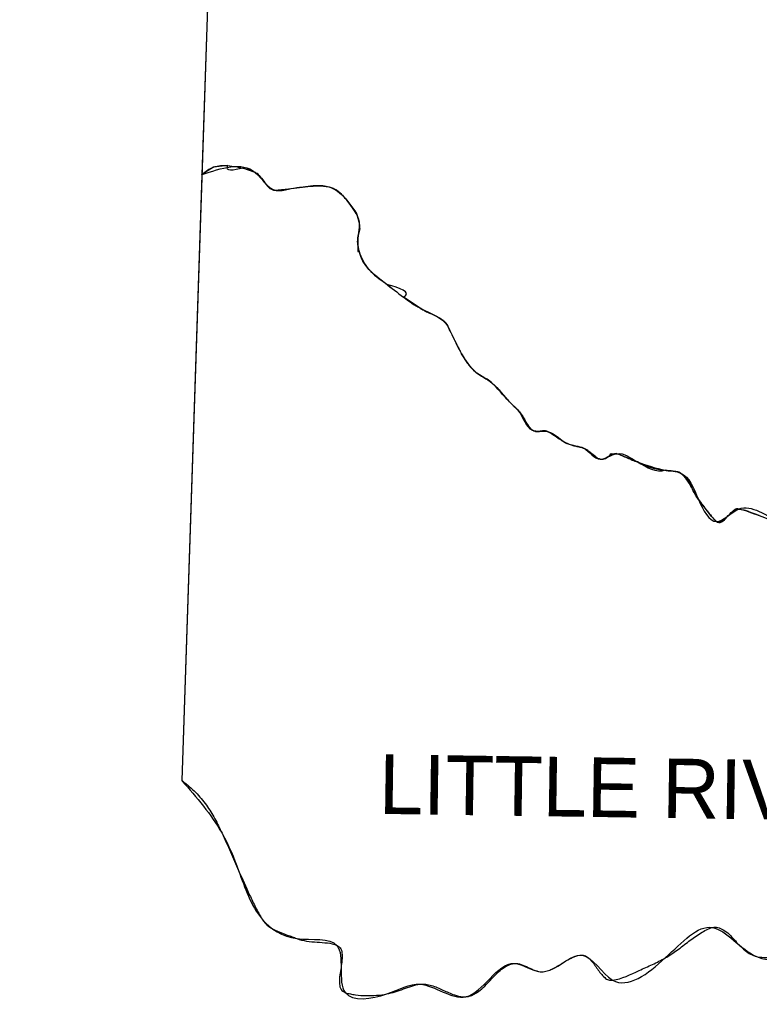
# Model space of a CAD drawing. Extents: x -12863 to 18921, y -8840 to 11152.
# Drawn here: x 10745 to 11268, y 5871 to 6570 of the extents above; entities that cross this region are included whole.
import ezdxf

# ---------------------------------------------------------------- set-up
doc = ezdxf.new("R2010")
doc.units = 0
for name, color, linetype in [('Level 1', 7, 'Continuous'), ('Level 2', 7, 'Continuous'), ('Level 48', 7, 'Continuous')]:
    doc.layers.add(name, color=color, linetype=linetype)

msp = doc.modelspace()

# ---------------------------------------------------------------- linework, layer by layer
at = {"layer": 'Level 1'}
msp.add_lwpolyline([(10745.390580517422, 10312.988270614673), (10947.920791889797, 8686.876140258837), (10859.864178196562, 6032.458444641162)], dxfattribs=at)
for points in [[(10873.808778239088, 6460.255811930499), (10911.719739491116, 6461.9790375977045), (10926.395841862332, 6449.259748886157), (10935.201503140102, 6450.2381557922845), (10950.856012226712, 6452.194969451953), (10965.532114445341, 6451.216562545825), (10976.29458949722, 6442.410901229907), (10985.100250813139, 6426.7563921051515), (10984.121844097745, 6412.080289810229), (10985.100250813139, 6406.209849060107), (10991.949098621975, 6393.490560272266), (11003.689980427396, 6383.706492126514), (11016.409269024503, 6373.922423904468), (11028.150150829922, 6366.095169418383), (11047.71828719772, 6353.375880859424), (11049.675100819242, 6349.462253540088), (11057.502355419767, 6333.807744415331), (11067.286423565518, 6321.088455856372), (11079.027305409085, 6313.261201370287), (11091.746593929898, 6299.5635059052), (11097.617034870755, 6293.69306500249), (11107.401103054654, 6279.995369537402), (11118.163577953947, 6279.0169626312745), (11132.839680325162, 6270.211301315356), (11143.602155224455, 6267.276080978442), (11155.343037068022, 6259.448826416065), (11167.083918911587, 6263.362453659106), (11181.760021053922, 6257.492012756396), (11201.328157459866, 6251.621571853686), (11212.090632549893, 6249.664758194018), (11224.809921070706, 6231.07502857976), (11237.529209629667, 6215.420519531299), (11253.183718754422, 6224.226180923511), (11282.535923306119, 6215.420519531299), (11301.125652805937, 6214.442112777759), (11317.758568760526, 6219.33414677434), (11330.477857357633, 6218.3557400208), (11353.959620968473, 6212.485299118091), (11368.6357231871, 6212.485299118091), (11384.29023227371, 6206.614858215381), (11398.966334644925, 6194.873976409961), (11408.750402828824, 6182.154687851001), (11408.750402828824, 6176.284246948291)], [(10859.864178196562, 6032.458444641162), (10888.237975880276, 5995.2789855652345), (10899.978857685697, 5968.862001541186), (10916.611773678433, 5934.61776295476), (10941.071944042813, 5920.920067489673), (10969.44574172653, 5916.028033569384), (10975.31618262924, 5882.7622016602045), (11004.668387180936, 5881.783794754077), (11028.150150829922, 5888.632642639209), (11060.437575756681, 5879.826981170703), (11094.681814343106, 5903.308744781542), (11114.249950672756, 5897.438303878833), (11142.62374850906, 5909.179185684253), (11164.148698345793, 5891.567862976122), (11201.328157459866, 5907.222372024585), (11234.593989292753, 5928.747322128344), (11265.90300746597, 5908.200778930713), (11296.233618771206, 5905.2655584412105), (11332.434670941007, 5900.373524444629), (11360.80846877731, 5898.416710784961), (11386.24704589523, 5885.697422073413), (11404.836775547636, 5872.978133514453), (11400.923148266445, 5874.934947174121)]]:
    msp.add_spline(points, degree=3, dxfattribs=at)
at = {"layer": 'Level 48'}
for p, q in [((10886.922977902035, 6848.1309279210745), (10874.066136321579, 6460.56858172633)), ((10882.258544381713, 6465.782325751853), (10874.066136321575, 6460.568581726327)), ((10892.452894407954, 6466.775410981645), (10882.258544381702, 6465.782325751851)), ((10911.719739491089, 6461.979037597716), (10902.867266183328, 6465.017695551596)), ((10922.117184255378, 6450.676342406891), (10918.581005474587, 6454.562636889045)), ((10923.79852432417, 6449.66703817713), (10922.117184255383, 6450.676342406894)), ((10935.201503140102, 6450.2381557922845), (10930.347465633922, 6449.67052545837)), ((10950.856012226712, 6452.194969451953), (10935.2015031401, 6450.2381557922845)), ((10957.04053232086, 6452.549243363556), (10954.516666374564, 6452.508872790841)), ((10958.191846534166, 6452.510839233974), (10957.040532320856, 6452.549243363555)), ((10959.4667736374, 6452.422172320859), (10958.191846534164, 6452.510839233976)), ((10961.868135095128, 6452.110269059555), (10959.4667736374, 6452.4221723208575)), ((10965.532114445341, 6451.216562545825), (10961.868135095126, 6452.110269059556)), ((10967.007369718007, 6450.652832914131), (10965.532114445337, 6451.216562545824)), ((10968.705117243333, 6449.758051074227), (10967.007369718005, 6450.652832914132)), ((10971.436402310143, 6447.699975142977), (10969.053548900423, 6449.539069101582)), ((10973.906162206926, 6445.1987775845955), (10973.14090073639, 6446.029826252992)), ((10979.265522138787, 6438.708332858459), (10976.29458949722, 6442.410901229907)), ((10980.482651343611, 6437.034057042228), (10979.265522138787, 6438.70833285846)), ((10981.840854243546, 6434.9515437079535), (10980.482651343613, 6437.034057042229)), ((10982.959618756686, 6432.944562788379), (10981.840854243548, 6434.951543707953)), ((10983.844469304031, 6431.010806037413), (10982.959618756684, 6432.944562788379)), ((10985.100250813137, 6426.75639210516), (10983.84446930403, 6431.010806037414)), ((10985.270112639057, 6423.095004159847), (10985.248032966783, 6425.695497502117)), ((10984.231786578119, 6415.740474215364), (10984.797583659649, 6419.417538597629)), ((10984.457944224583, 6409.075231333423), (10984.121844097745, 6412.080289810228)), ((10986.275401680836, 6402.698228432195), (10985.100250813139, 6406.209849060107)), ((10986.738361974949, 6401.509284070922), (10986.275401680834, 6402.698228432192)), ((10987.719075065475, 6399.330635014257), (10986.738361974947, 6401.509284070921)), ((10988.116172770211, 6398.564595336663), (10987.719075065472, 6399.33063501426)), ((10991.949098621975, 6393.490560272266), (10988.11617277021, 6398.564595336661)), ((11004.762862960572, 6382.865238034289), (11003.689980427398, 6383.706492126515)), ((11028.150150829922, 6366.095169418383), (11016.409269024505, 6373.922423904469)), ((11030.12817980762, 6364.90805326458), (11028.150150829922, 6366.095169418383)), ((11030.708029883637, 6364.598016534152), (11030.128179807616, 6364.908053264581)), ((11033.45112766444, 6363.270093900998), (11030.70802988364, 6364.5980165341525)), ((11042.637566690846, 6358.7449020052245), (11039.05862080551, 6360.730474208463)), ((11057.502592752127, 6333.807269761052), (11057.502355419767, 6333.807744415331)), ((11061.83770859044, 6327.070311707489), (11057.502592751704, 6333.8072697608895)), ((11064.458603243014, 6323.9964200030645), (11063.786432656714, 6324.742520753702)), ((11067.286423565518, 6321.088455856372), (11064.458603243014, 6323.996420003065)), ((11068.190158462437, 6320.28538685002), (11067.286423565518, 6321.088455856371)), ((11070.098240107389, 6318.937561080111), (11068.190158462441, 6320.28538685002)), ((11073.206353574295, 6317.191325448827), (11070.098240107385, 6318.937561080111)), ((11078.699104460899, 6313.585436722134), (11076.289722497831, 6315.43684139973)), ((11079.027305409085, 6313.261201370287), (11078.699104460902, 6313.5854367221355)), ((11099.062292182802, 6292.012390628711), (11097.617034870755, 6293.69306500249)), ((11100.187171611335, 6290.397710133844), (11099.0622921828, 6292.012390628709)), ((11104.580899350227, 6283.157013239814), (11102.342357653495, 6286.755076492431)), ((11106.614270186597, 6280.7234368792), (11105.954457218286, 6281.421193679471)), ((11109.708422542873, 6279.043975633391), (11108.432387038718, 6279.36383961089)), ((11112.399679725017, 6279.121924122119), (11109.708422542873, 6279.043975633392)), ((11118.163577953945, 6279.016962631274), (11117.76441858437, 6279.174845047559)), ((11121.8571332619, 6276.959251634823), (11118.163577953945, 6279.0169626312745)), ((11129.0616772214, 6272.141972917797), (11125.445330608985, 6274.529439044)), ((11138.236356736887, 6268.691920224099), (11135.481171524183, 6269.350950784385)), ((11152.252686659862, 6261.040687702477), (11149.415994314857, 6263.304125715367)), ((11161.21461102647, 6261.429646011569), (11158.260801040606, 6259.7266437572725)), ((11166.888575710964, 6263.420988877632), (11164.167854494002, 6263.1206452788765)), ((11167.083918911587, 6263.362453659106), (11166.888575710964, 6263.420988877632)), ((11170.752473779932, 6261.975568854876), (11167.083918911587, 6263.362453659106)), ((11178.065503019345, 6258.843101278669), (11174.404661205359, 6260.403369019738)), ((11179.368624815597, 6258.330565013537), (11178.065503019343, 6258.843101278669)), ((11181.760021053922, 6257.492012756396), (11179.368624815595, 6258.330565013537)), ((11204.042213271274, 6251.212753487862), (11201.328157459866, 6251.621571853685)), ((11206.838455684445, 6251.120013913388), (11205.438471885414, 6251.161549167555)), ((11210.86597587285, 6250.360576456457), (11206.838455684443, 6251.120013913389)), ((11216.177982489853, 6245.638671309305), (11213.81683423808, 6248.2501144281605)), ((11218.858646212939, 6241.471354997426), (11216.177982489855, 6245.638671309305)), ((11219.178413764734, 6240.890995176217), (11218.858646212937, 6241.471354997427)), ((11222.973978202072, 6233.834891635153), (11221.814776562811, 6235.882768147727)), ((11223.222322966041, 6233.42502253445), (11222.973978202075, 6233.834891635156)), ((11224.809921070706, 6231.07502857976), (11223.222322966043, 6233.42502253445)), ((11230.357289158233, 6223.60935521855), (11224.809921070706, 6231.07502857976)), ((11230.845725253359, 6222.975686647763), (11230.357289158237, 6223.609355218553)), ((11234.03056191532, 6219.08963479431), (11231.070780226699, 6222.686578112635)), ((11256.218809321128, 6223.567021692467), (11253.183718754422, 6224.2261809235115)), ((11267.704606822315, 6219.660495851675), (11260.427692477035, 6222.3131059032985)), ((11237.529209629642, 6215.420519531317), (11234.03056191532, 6219.089634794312)), ((11241.035710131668, 6215.165944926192), (11239.233102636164, 6214.635008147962)), ((11244.884165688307, 6218.622106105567), (11241.035710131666, 6215.165944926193))]:
    msp.add_line(p, q, dxfattribs=at)
msp.add_lwpolyline([(10874.066136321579, 6460.56858172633), (10874.055489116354, 6460.247627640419), (10859.864178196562, 6032.458444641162)], dxfattribs=at)
for points in [[(10874.066136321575, 6460.568581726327), (10882.258544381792, 6465.782325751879), (10892.45289440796, 6466.775410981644), (10902.867266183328, 6465.017695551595), (10911.719739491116, 6461.9790375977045), (10915.283219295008, 6458.977309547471), (10918.58100547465, 6454.562636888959), (10922.11718425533, 6450.676342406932), (10926.395841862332, 6449.259748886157), (10935.201503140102, 6450.2381557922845), (10950.856012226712, 6452.194969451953), (10954.516666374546, 6452.50887279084), (10958.191846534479, 6452.510839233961), (10961.86813509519, 6452.110269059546), (10965.532114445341, 6451.216562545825), (10968.70511724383, 6449.75805107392), (10971.436402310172, 6447.69997514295), (10973.906162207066, 6445.198777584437), (10976.29458949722, 6442.410901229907), (10979.26552213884, 6438.708332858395), (10981.84085424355, 6434.951543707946), (10983.844469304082, 6431.010806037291), (10985.100250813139, 6426.7563921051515), (10985.270112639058, 6423.095004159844), (10984.797583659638, 6419.417538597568), (10984.231786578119, 6415.740474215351), (10984.121844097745, 6412.080289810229), (10985.100250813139, 6406.209849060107), (10986.275401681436, 6402.698228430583), (10987.71907506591, 6399.330635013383), (10991.949098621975, 6393.490560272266), (11003.689980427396, 6383.706492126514), (11016.409269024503, 6373.922423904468), (11028.150150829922, 6366.095169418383), (11030.7080298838, 6364.598016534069), (11033.451127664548, 6363.270093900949), (11039.058620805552, 6360.7304742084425), (11044.103913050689, 6357.693379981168), (11047.71828719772, 6353.375880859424), (11049.675100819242, 6349.462253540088), (11057.502355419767, 6333.807744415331), (11061.837708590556, 6327.07031170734), (11064.458603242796, 6323.996420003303), (11067.286423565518, 6321.088455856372), (11070.09824010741, 6318.937561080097), (11073.206353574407, 6317.191325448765), (11076.289722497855, 6315.436841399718), (11079.027305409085, 6313.261201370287), (11091.746593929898, 6299.5635059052), (11097.617034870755, 6293.69306500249), (11100.18717161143, 6290.397710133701), (11102.34235765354, 6286.755076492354), (11104.580899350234, 6283.157013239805), (11105.887149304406, 6281.497148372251), (11106.614270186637, 6280.723436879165), (11107.401103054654, 6279.995369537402), (11109.708422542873, 6279.043975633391), (11112.39967972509, 6279.121924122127), (11115.182477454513, 6279.431464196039), (11117.76441858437, 6279.174845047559)], [(10902.867266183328, 6465.017695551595), (10892.45289440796, 6466.775410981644), (10892.452894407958, 6466.775410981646)], [(10954.516666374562, 6452.50887279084), (10954.516666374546, 6452.50887279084), (10950.856012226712, 6452.194969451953)], [(10969.053548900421, 6449.539069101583), (10968.70511724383, 6449.75805107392), (10968.705117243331, 6449.7580510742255)], [(10973.140900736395, 6446.029826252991), (10971.436402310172, 6447.69997514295), (10971.436402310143, 6447.699975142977)], [(10975.65318804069, 6443.176214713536), (10973.906162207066, 6445.198777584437), (10973.906162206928, 6445.1987775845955)], [(10976.29458949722, 6442.410901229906), (10976.29458949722, 6442.410901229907), (10975.653188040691, 6443.176214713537)], [(10984.797583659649, 6419.4175385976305), (10985.270112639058, 6423.095004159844), (10985.270112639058, 6423.095004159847)], [(10985.248032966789, 6425.695497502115), (10985.100250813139, 6426.7563921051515), (10985.100250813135, 6426.756392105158)], [(10984.092487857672, 6414.077891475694), (10984.231786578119, 6415.740474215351), (10984.231786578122, 6415.740474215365)], [(10984.121844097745, 6412.080289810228), (10984.121844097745, 6412.080289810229), (10984.09248785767, 6414.077891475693)], [(10985.100250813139, 6406.209849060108), (10985.100250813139, 6406.209849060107), (10984.457944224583, 6409.075231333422)], [(11016.409269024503, 6373.922423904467), (11016.409269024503, 6373.922423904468), (11004.762862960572, 6382.865238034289)], [(11039.058620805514, 6360.730474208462), (11033.451127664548, 6363.270093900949), (11033.451127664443, 6363.270093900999)], [(11044.103913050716, 6357.693379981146), (11044.103913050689, 6357.693379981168), (11042.637566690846, 6358.744902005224)], [(11063.786432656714, 6324.742520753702), (11061.837708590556, 6327.07031170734), (11061.837708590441, 6327.070311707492)], [(11076.289722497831, 6315.436841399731), (11073.206353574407, 6317.191325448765), (11073.206353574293, 6317.191325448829)], [(11102.342357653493, 6286.755076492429), (11100.18717161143, 6290.397710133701), (11100.18717161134, 6290.397710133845)], [(11107.401103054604, 6279.995369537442), (11106.614270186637, 6280.723436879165), (11106.614270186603, 6280.7234368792)], [(11108.432387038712, 6279.363839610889), (11107.401103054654, 6279.995369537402), (11107.401103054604, 6279.995369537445)], [(11117.76441858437, 6279.174845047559), (11118.163577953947, 6279.0169626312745), (11121.85713326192, 6276.95925163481), (11125.445330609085, 6274.529439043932), (11129.061677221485, 6272.141972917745), (11132.839680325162, 6270.211301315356), (11135.481171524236, 6269.350950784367), (11138.236356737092, 6268.691920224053), (11140.98382246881, 6268.058775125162), (11143.602155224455, 6267.276080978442), (11146.607602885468, 6265.596727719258), (11149.415994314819, 6263.304125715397), (11152.252686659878, 6261.040687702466), (11155.343037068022, 6259.448826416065), (11158.26080104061, 6259.726643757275), (11161.214611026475, 6261.429646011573), (11164.167854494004, 6263.1206452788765), (11167.083918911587, 6263.362453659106), (11170.752473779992, 6261.975568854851), (11174.404661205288, 6260.403369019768), (11178.06550301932, 6258.843101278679), (11181.760021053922, 6257.492012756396), (11201.328157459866, 6251.621571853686), (11204.042213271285, 6251.212753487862), (11206.838455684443, 6251.120013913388), (11210.865975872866, 6250.360576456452), (11211.488344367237, 6250.050442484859), (11212.090632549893, 6249.664758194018), (11216.177982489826, 6245.638671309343), (11219.178413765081, 6240.8909951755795), (11221.814776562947, 6235.882768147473), (11223.222322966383, 6233.425022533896), (11224.809921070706, 6231.07502857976), (11230.84572525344, 6222.975686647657), (11234.030561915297, 6219.08963479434), (11237.529209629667, 6215.420519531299), (11239.233102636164, 6214.635008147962), (11241.035710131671, 6215.165944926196), (11244.884165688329, 6218.622106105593), (11248.968770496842, 6222.678889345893), (11251.066564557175, 6223.960603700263), (11253.183718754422, 6224.226180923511), (11260.427692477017, 6222.313105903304), (11267.704606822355, 6219.66049585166), (11275.05912827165, 6217.08931298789), (11282.535923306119, 6215.420519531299), (11291.84857532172, 6214.4588634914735), (11301.125652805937, 6214.442112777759), (11305.311669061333, 6215.366819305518), (11309.434506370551, 6216.969677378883), (11313.561145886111, 6218.531761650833), (11317.758568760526, 6219.33414677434), (11330.477857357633, 6218.3557400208), (11336.378724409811, 6217.027499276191), (11342.227892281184, 6215.387469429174), (11348.07248359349, 6213.763964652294), (11353.959620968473, 6212.485299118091), (11357.592390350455, 6212.258835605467), (11361.277990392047, 6212.485799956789), (11364.973431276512, 6212.712513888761), (11368.6357231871, 6212.485299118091), (11384.29023227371, 6206.614858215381), (11398.966334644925, 6194.873976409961), (11408.750402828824, 6182.154687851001), (11408.750402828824, 6176.284246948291)], [(11125.445330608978, 6274.529439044), (11121.85713326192, 6276.95925163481), (11121.857133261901, 6276.959251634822)], [(11140.983822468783, 6268.05877512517), (11138.236356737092, 6268.691920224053), (11138.236356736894, 6268.691920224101)], [(11149.415994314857, 6263.304125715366), (11149.415994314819, 6263.304125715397), (11146.607602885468, 6265.596727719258), (11146.607602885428, 6265.596727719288)], [(11164.167854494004, 6263.120645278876), (11164.167854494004, 6263.1206452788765), (11161.214611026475, 6261.429646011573), (11161.214611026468, 6261.429646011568)], [(11174.404661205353, 6260.403369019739), (11174.404661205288, 6260.403369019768), (11170.752473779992, 6261.975568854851), (11170.75247377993, 6261.975568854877)], [(11201.328157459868, 6251.621571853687), (11201.328157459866, 6251.621571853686), (11181.760021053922, 6257.492012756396)], [(11205.438471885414, 6251.161549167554), (11204.042213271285, 6251.212753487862), (11204.04221327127, 6251.212753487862)], [(11213.816834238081, 6248.25011442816), (11212.090632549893, 6249.664758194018), (11212.090632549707, 6249.664758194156)], [(11221.814776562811, 6235.882768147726), (11219.178413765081, 6240.8909951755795), (11219.178413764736, 6240.890995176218)], [(11231.070780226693, 6222.686578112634), (11230.84572525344, 6222.975686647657), (11230.845725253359, 6222.975686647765)], [(11248.968770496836, 6222.678889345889), (11244.884165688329, 6218.622106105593), (11244.884165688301, 6218.622106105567)], [(11239.233102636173, 6214.63500814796), (11237.529209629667, 6215.420519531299), (11237.529209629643, 6215.420519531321)], [(10859.864178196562, 6032.458444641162), (10862.565117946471, 6030.414602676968), (10865.089926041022, 6028.338088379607), (10869.656108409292, 6024.083062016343), (10877.169465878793, 6015.137152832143), (10883.123628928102, 6005.55702478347), (10888.237975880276, 5995.2789855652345), (10899.978857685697, 5968.862001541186), (10907.751321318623, 5951.60309747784), (10911.916740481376, 5943.0645356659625), (10914.18195427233, 5938.828213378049), (10916.611773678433, 5934.61776295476), (10921.325300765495, 5929.502604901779), (10927.50390806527, 5926.016457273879), (10934.351490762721, 5923.406538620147), (10937.777365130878, 5922.194920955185), (10941.071944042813, 5920.920067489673), (10947.999604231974, 5919.115186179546), (10955.345840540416, 5918.447405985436), (10962.648578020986, 5917.792948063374), (10969.44574172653, 5916.028033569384), (10972.124135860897, 5913.525793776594), (10973.058259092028, 5909.523046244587), (10972.071040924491, 5899.07076390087), (10971.23878338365, 5888.780658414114), (10972.366607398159, 5884.980631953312), (10975.31618262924, 5882.7622016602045), (10978.893405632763, 5881.817135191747), (10982.55019178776, 5881.151732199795), (10989.99578585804, 5880.570741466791), (10997.439629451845, 5880.840879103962), (11004.668387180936, 5881.783794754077), (11010.538406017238, 5883.275230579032), (11016.406759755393, 5885.315713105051), (11022.276368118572, 5887.302448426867), (11028.150150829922, 5888.632642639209), (11032.17638841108, 5888.646689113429), (11036.212105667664, 5887.780235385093), (11044.298557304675, 5884.529825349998), (11052.382661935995, 5881.12940859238), (11058.428051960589, 5879.832964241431), (11060.437575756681, 5879.826981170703), (11062.869901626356, 5880.211609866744), (11069.579374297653, 5883.659419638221), (11077.70493593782, 5891.388372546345), (11085.75787713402, 5899.207070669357), (11090.051995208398, 5901.96045880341), (11094.681814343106, 5903.308744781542), (11099.514701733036, 5902.643557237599), (11104.440363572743, 5900.566358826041), (11109.37878488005, 5898.392743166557), (11114.249950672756, 5897.438303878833), (11117.861066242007, 5898.0050355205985), (11121.461008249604, 5899.380608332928), (11128.61292393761, 5903.45538289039), (11135.676802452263, 5907.456838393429), (11140.899554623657, 5909.082894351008), (11142.62374850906, 5909.179185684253), (11145.603067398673, 5908.273508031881), (11148.358079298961, 5906.020330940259), (11153.478824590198, 5899.4260557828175), (11158.553269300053, 5893.305514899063), (11161.250405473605, 5891.644505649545), (11164.148698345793, 5891.567862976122), (11182.879335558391, 5898.334242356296), (11192.389269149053, 5902.627254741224), (11201.328157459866, 5907.222372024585), (11209.65749163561, 5912.674856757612), (11217.976473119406, 5918.969171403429), (11226.287754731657, 5924.771323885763), (11230.441337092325, 5927.07096679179), (11232.517758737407, 5927.997477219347), (11234.593989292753, 5928.747322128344), (11242.308487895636, 5927.124417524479), (11249.926051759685, 5920.232740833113), (11257.704838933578, 5912.461718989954), (11265.90300746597, 5908.200778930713), (11273.114134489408, 5907.449400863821), (11280.748690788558, 5906.800998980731), (11288.543058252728, 5906.118681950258), (11296.233618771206, 5905.2655584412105), (11314.333712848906, 5902.814273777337), (11332.434670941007, 5900.373524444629), (11339.514702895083, 5899.82733947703), (11346.631075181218, 5899.664319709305), (11353.742694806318, 5899.366698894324), (11357.283880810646, 5899.005611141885), (11360.80846877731, 5898.416710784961), (11367.549928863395, 5896.253236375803), (11373.876423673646, 5893.036265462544), (11380.028585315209, 5889.329695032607), (11386.24704589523, 5885.697422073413), (11389.905387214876, 5883.605693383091), (11394.134921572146, 5881.001672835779), (11401.970630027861, 5875.762733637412)]]:
    msp.add_spline(points, degree=3, dxfattribs=at)
for points, degree in [([(10918.581005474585, 6454.562636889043), (10917.430290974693, 6456.003747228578), (10916.471606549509, 6457.55226848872), (10915.283219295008, 6458.977309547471), (10914.278393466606, 6460.182235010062), (10913.13395669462, 6461.225583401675), (10911.719739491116, 6461.9790375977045), (10911.719739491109, 6461.979037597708), (10911.719739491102, 6461.979037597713), (10911.719739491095, 6461.979037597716)], 3), ([(10930.347465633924, 6449.670525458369), (10929.029137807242, 6449.524700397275), (10927.711093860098, 6449.386789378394), (10926.395841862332, 6449.259748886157), (10925.465835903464, 6449.169919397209), (10924.605501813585, 6449.326626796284), (10923.798524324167, 6449.667038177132)], 3), ([(11003.689980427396, 6383.706492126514), (10999.666730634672, 6386.8415236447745), (10995.753285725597, 6389.955712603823), (10991.949098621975, 6393.490560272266)], 2), ([(11047.71828719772, 6353.375880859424), (11046.84850629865, 6355.1154403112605), (11045.595452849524, 6356.511110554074), (11044.103913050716, 6357.693379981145)], 2), ([(11049.675583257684, 6349.461288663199), (11049.675422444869, 6349.4616102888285), (11049.675261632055, 6349.461931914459), (11049.675100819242, 6349.462253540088), (11049.02282960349, 6350.766795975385), (11048.370558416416, 6352.0713384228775), (11047.71828719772, 6353.375880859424)], 3), ([(11057.502355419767, 6333.807744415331), (11054.893431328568, 6339.0255924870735), (11052.284507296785, 6344.243440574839), (11049.675583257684, 6349.461288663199)], 2), ([(11097.617034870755, 6293.69306500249), (11095.681260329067, 6295.659999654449), (11093.669945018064, 6297.580071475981), (11091.746593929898, 6299.5635059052), (11087.416086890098, 6304.029293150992), (11083.36818903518, 6308.803430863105), (11079.027305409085, 6313.261201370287)], 3), ([(11105.95445721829, 6281.421193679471), (11105.931917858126, 6281.446386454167), (11105.909478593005, 6281.471699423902), (11105.887149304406, 6281.497148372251), (11105.42147781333, 6282.027879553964), (11104.966986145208, 6282.566692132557), (11104.580899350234, 6283.157013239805), (11104.580899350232, 6283.157013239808), (11104.58089935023, 6283.157013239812), (11104.580899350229, 6283.157013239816)], 3), ([(11117.76441858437, 6279.174845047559), (11116.94504853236, 6279.451726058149), (11116.042176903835, 6279.478265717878), (11115.182477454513, 6279.431464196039), (11114.254755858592, 6279.380959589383), (11113.327364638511, 6279.199359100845), (11112.39967972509, 6279.121924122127), (11112.399679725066, 6279.121924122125), (11112.399679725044, 6279.121924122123), (11112.399679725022, 6279.1219241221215)], 3), ([(11135.48117152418, 6269.350950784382), (11134.581166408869, 6269.570129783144), (11133.704534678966, 6269.864544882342), (11132.839680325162, 6270.211301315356), (11131.518854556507, 6270.740875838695), (11130.249629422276, 6271.371321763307), (11129.061677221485, 6272.141972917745), (11129.061677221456, 6272.141972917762), (11129.061677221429, 6272.141972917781), (11129.061677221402, 6272.141972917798)], 3), ([(11146.60760288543, 6265.596727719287), (11145.651149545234, 6266.294409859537), (11144.661853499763, 6266.889883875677), (11143.602155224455, 6267.276080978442), (11142.764390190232, 6267.581396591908), (11141.884867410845, 6267.8325482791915), (11140.98382246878, 6268.0587751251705)], 3), ([(11158.260801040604, 6259.7266437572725), (11157.412679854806, 6259.240497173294), (11156.258791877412, 6259.158359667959), (11155.343037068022, 6259.448826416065), (11154.256912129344, 6259.7933325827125), (11153.166115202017, 6260.320946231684), (11152.252686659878, 6261.040687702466), (11152.252686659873, 6261.04068770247), (11152.252686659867, 6261.040687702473), (11152.252686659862, 6261.040687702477)], 3), ([(11212.090632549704, 6249.664758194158), (11211.696309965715, 6249.948989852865), (11211.287072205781, 6250.177078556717), (11210.86597587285, 6250.360576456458)], 2), ([(11253.183718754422, 6224.226180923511), (11251.768768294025, 6224.4742338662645), (11250.357907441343, 6223.785685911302), (11248.968770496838, 6222.678889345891)], 2), ([(11260.427692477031, 6222.3131059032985), (11259.023365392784, 6222.781602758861), (11257.620890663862, 6223.208513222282), (11256.218809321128, 6223.567021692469)], 2)]:
    msp.add_open_spline(points, degree=degree, dxfattribs=at)

# ---------------------------------------------------------------- texts
at = {"layer": 'Level 2'}
msp.add_text('LITTLE RIVER', height=42.073449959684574, rotation=359.1696833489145, dxfattribs=at).set_placement((10998.797946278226, 6008.976681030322))

doc.saveas('drawing.dxf')
